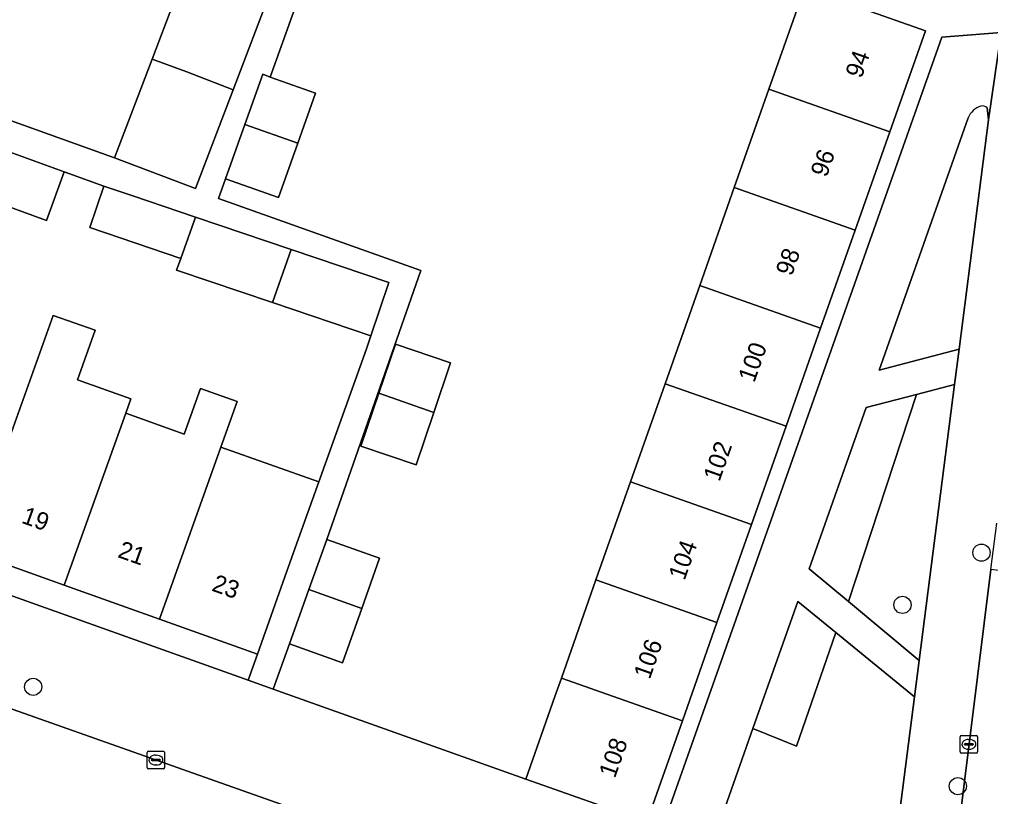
# Model space of a CAD drawing. Extents: x 159817 to 160765, y 380688 to 381638.
# Drawn here: x 160164.7 to 160220, y 381132.6 to 381176.8 of the extents above; entities that cross this region are included whole.
import ezdxf

# ---------------------------------------------------------------- set-up
doc = ezdxf.new("R2010")
doc.units = 0
for name, color, linetype in [('IMGEO_Boom', 7, 'Continuous'), ('IMGEO_Erf', 7, 'Continuous'), ('IMGEO_Groenvoorziening', 7, 'Continuous'), ('IMGEO_Kolk', 7, 'Continuous'), ('IMGEO_Pand', 7, 'Continuous'), ('IMGEO_Pand_nummerreeks', 7, 'Continuous'), ('IMGEO_Rijbaan_lokaal_open', 7, 'Continuous'), ('IMGEO_Voetpad_open', 7, 'Continuous')]:
    doc.layers.add(name, color=color, linetype=linetype)

msp = doc.modelspace()

# ---------------------------------------------------------------- linework, layer by layer
at = {"layer": 'IMGEO_Boom'}
for centre in [(160219.439, 381146.455), (160214.942, 381143.481), (160165.453, 381138.815), (160218.097, 381133.158)]:
    msp.add_circle(centre, 0.489, dxfattribs=at)
at = {"layer": 'IMGEO_Erf'}
for points in [[(160221.046, 381210.796), (160219.568, 381205.05), (160218.089, 381199.304), (160216.611, 381193.558), (160215.133, 381187.812), (160213.612, 381181.902), (160213.015, 381179.581), (160212.48, 381177.505), (160216.252, 381176.177), (160214.223, 381170.416), (160212.254, 381164.828), (160210.286, 381159.24), (160208.318, 381153.652), (160206.349, 381148.063), (160204.38, 381142.474), (160202.412, 381136.886), (160200.384, 381131.129), (160201.281, 381130.825), (160217.187, 381175.81), (160220.553, 381176.081)], [(160180.822, 381178.783), (160178.953, 381173.541), (160181.534, 381172.621), (160180.517, 381169.768), (160179.414, 381166.673), (160176.404, 381167.746), (160176.005, 381166.626), (160187.531, 381162.518), (160182.165, 381147.21), (160185.175, 381146.137), (160184.158, 381143.284), (160183.055, 381140.189), (160180.045, 381141.262), (160179.125, 381138.685), (160193.497, 381133.554), (160195.158, 381138.27), (160195.525, 381139.312), (160197.493, 381144.9), (160199.462, 381150.488), (160201.431, 381156.077), (160203.399, 381161.665), (160205.368, 381167.254), (160207.336, 381172.842), (160209.365, 381178.602)], [(160153.991, 381174.716), (160170.088, 381168.945), (160172.23, 381174.562), (160173.43, 381177.709)], [(160164.323, 381153.577), (160166.602, 381159.968), (160168.981, 381159.12), (160167.971, 381156.289), (160171.007, 381155.206), (160170.72, 381154.4), (160174.059, 381153.21), (160174.981, 381155.797), (160177.059, 381155.056), (160176.137, 381152.469), (160181.717, 381150.479), (160184.422, 381158.059), (160184.673, 381158.799), (160179.07, 381160.697), (160173.676, 381162.524), (160173.623, 381162.542), (160173.862, 381163.212), (160168.679, 381164.967), (160169.481, 381167.334), (160167.489, 381168.053), (160167.223, 381168.149), (160166.219, 381165.378), (160162.869, 381166.591)]]:
    msp.add_lwpolyline(points, dxfattribs=at)
for points in [[(160185.139, 381155.531), (160186.086, 381158.328), (160189.222, 381157.266), (160188.263, 381154.431), (160187.253, 381151.448), (160184.116, 381152.51)], [(160156.395, 381148.463), (160150.978, 381150.394), (160145.562, 381152.324), (160140.147, 381154.254), (160134.567, 381156.243), (160134.027, 381154.785), (160177.694, 381139.196), (160178.225, 381140.682), (160172.644, 381142.671), (160167.227, 381144.602), (160161.811, 381146.532)]]:
    msp.add_lwpolyline(points, close=True, dxfattribs=at)
at = {"layer": 'IMGEO_Groenvoorziening'}
for points in [[(160219.848, 381171.104), (160219.756, 381171.779)], [(160218.686, 381171.22), (160213.62, 381156.844), (160218.169, 381158.049), (160219.848, 381171.104)], [(160215.622, 381138.248), (160211.146, 381141.909), (160208.918, 381135.436), (160206.428, 381136.435), (160204.587, 381131.21)], [(160214.532, 381129.693), (160215.622, 381138.248)]]:
    msp.add_lwpolyline(points, dxfattribs=at)
for points in [[(160215.888, 381140.319), (160217.909, 381156.029), (160215.733, 381155.464), (160211.864, 381143.673)], [(160211.864, 381143.673), (160215.733, 381155.464), (160212.872, 381154.722), (160209.633, 381145.53)], [(160206.428, 381136.435), (160208.918, 381135.436), (160211.146, 381141.909), (160208.981, 381143.679)]]:
    msp.add_lwpolyline(points, close=True, dxfattribs=at)
for centre, radius, start, end in [((160219.75, 381170.795), 1.146, 107.4196, 158.2101), ((160219.491, 381171.545), 0.354, 41.5289, 103.7817)]:
    msp.add_arc(centre, radius, start, end, dxfattribs=at)
at = {"layer": 'IMGEO_Kolk'}
for p, q in [((160218.222, 381135.112), (160218.222, 381135.964)), ((160218.297, 381136.038), (160219.149, 381136.038)), ((160218.524, 381135.581), (160218.922, 381135.581)), ((160218.71, 381135.818), (160218.735, 381135.818)), ((160219.223, 381135.964), (160219.223, 381135.112)), ((160171.939, 381134.218), (160171.939, 381135.07)), ((160172.014, 381135.144), (160172.866, 381135.144)), ((160172.94, 381135.07), (160172.94, 381134.218)), ((160219.149, 381135.038), (160218.297, 381135.038)), ((160218.481, 381135.532), (160218.481, 381135.544)), ((160218.919, 381135.495), (160218.521, 381135.495)), ((160218.733, 381135.258), (160218.708, 381135.258)), ((160218.965, 381135.544), (160218.965, 381135.532)), ((160172.198, 381134.638), (160172.198, 381134.65)), ((160172.636, 381134.601), (160172.238, 381134.601)), ((160172.241, 381134.687), (160172.639, 381134.687)), ((160172.427, 381134.924), (160172.452, 381134.924)), ((160172.682, 381134.65), (160172.682, 381134.638)), ((160172.866, 381134.144), (160172.014, 381134.144)), ((160172.45, 381134.364), (160172.425, 381134.364))]:
    msp.add_line(p, q, dxfattribs=at)
for points in [[(160218.222, 381135.112), (160218.222, 381135.964)], [(160218.297, 381136.038), (160219.149, 381136.038)], [(160219.223, 381135.964), (160219.223, 381135.112)], [(160171.939, 381134.218), (160171.939, 381135.07)], [(160172.014, 381135.144), (160172.866, 381135.144)], [(160172.94, 381135.07), (160172.94, 381134.218)], [(160219.149, 381135.038), (160218.297, 381135.038)], [(160172.866, 381134.144), (160172.014, 381134.144)]]:
    msp.add_lwpolyline(points, dxfattribs=at)
for centre, radius, start, end in [((160218.299, 381135.962), 0.0765, 91.552, 178.448), ((160218.299, 381135.962), 0.0765, 91.552, 178.448), ((160218.521, 381135.541), 0.0403, 85.8775, 175.7526), ((160218.926, 381135.543), 0.0386, 1.7309, 96.639), ((160219.147, 381135.962), 0.0765, 1.552, 88.448), ((160219.147, 381135.962), 0.0765, 1.552, 88.448), ((160172.016, 381135.068), 0.0765, 91.552, 178.448), ((160172.016, 381135.068), 0.0765, 91.552, 178.448), ((160172.864, 381135.068), 0.0765, 1.552, 88.448), ((160172.864, 381135.068), 0.0765, 1.552, 88.448), ((160218.299, 381135.114), 0.0765, 181.552, 268.448), ((160218.299, 381135.114), 0.0765, 181.552, 268.448), ((160218.518, 381135.531), 0.0366, 178.938, 274.7102), ((160218.922, 381135.538), 0.043, 264.8664, 352.4533), ((160219.147, 381135.114), 0.0765, 271.552, 358.448), ((160219.147, 381135.114), 0.0765, 271.552, 358.448), ((160172.238, 381134.647), 0.0403, 85.8775, 175.7526), ((160172.235, 381134.637), 0.0366, 178.938, 274.7102), ((160172.639, 381134.644), 0.043, 264.8664, 352.4533), ((160172.643, 381134.649), 0.0386, 1.7309, 96.639), ((160172.016, 381134.22), 0.0765, 181.552, 268.448), ((160172.016, 381134.22), 0.0765, 181.552, 268.448), ((160172.864, 381134.22), 0.0765, 271.552, 358.448), ((160172.864, 381134.22), 0.0765, 271.552, 358.448)]:
    msp.add_arc(centre, radius, start, end, dxfattribs=at)
for centre, major_axis, ratio, start_param, end_param in [((160218.709, 381135.538), (-0.387, 0.002), 0.722429, 4.712389, 7.853982), ((160218.734, 381135.538), (-0.39, 0.002), 0.717154, 1.570796, 4.712389), ((160172.426, 381134.644), (-0.387, 0.002), 0.722429, 4.712389, 7.853982), ((160172.451, 381134.644), (-0.39, 0.002), 0.717154, 1.570796, 4.712389)]:
    msp.add_ellipse(centre, major_axis=major_axis, ratio=ratio, start_param=start_param, end_param=end_param, dxfattribs=at)
at = {"layer": 'IMGEO_Pand'}
for points in [[(160216.252, 381176.177), (160212.48, 381177.505), (160213.015, 381179.581), (160208.447, 381180.979), (160208.302, 381180.422), (160207.961, 381179.097), (160209.365, 381178.602), (160207.336, 381172.842), (160214.223, 381170.416)], [(160179.028, 381178.555), (160174.422, 381180.311), (160174.33, 381180.069), (160173.43, 381177.709), (160172.23, 381174.562), (160174.202, 381173.828), (160176.84, 381172.816)], [(160176.84, 381172.816), (160174.202, 381173.828), (160172.23, 381174.562), (160170.088, 381168.945), (160174.693, 381167.188)], [(160181.534, 381172.621), (160178.953, 381173.541), (160178.524, 381173.694), (160177.504, 381170.832), (160180.517, 381169.768)], [(160214.223, 381170.416), (160207.336, 381172.842), (160205.368, 381167.254), (160212.254, 381164.828)], [(160177.504, 381170.832), (160176.404, 381167.746), (160179.414, 381166.673), (160180.517, 381169.768)], [(160167.223, 381168.149), (160163.873, 381169.362), (160162.869, 381166.591), (160166.219, 381165.378)], [(160174.701, 381165.566), (160171.066, 381166.797), (160169.481, 381167.334), (160168.679, 381164.967), (160173.862, 381163.212)], [(160203.399, 381161.665), (160210.286, 381159.24), (160212.254, 381164.828), (160205.368, 381167.254)], [(160180.148, 381163.721), (160174.701, 381165.566), (160173.862, 381163.212), (160173.623, 381162.542), (160173.676, 381162.524), (160179.07, 381160.697)], [(160185.702, 381161.84), (160180.148, 381163.721), (160179.07, 381160.697), (160184.673, 381158.799)], [(160203.399, 381161.665), (160201.431, 381156.077), (160208.318, 381153.652), (160210.286, 381159.24)], [(160169.738, 381151.646), (160170.72, 381154.4), (160171.007, 381155.206), (160167.971, 381156.289), (160168.981, 381159.12), (160166.602, 381159.968), (160164.323, 381153.577), (160161.811, 381146.532), (160167.227, 381144.602)], [(160185.139, 381155.531), (160188.263, 381154.431), (160189.222, 381157.266), (160186.086, 381158.328)], [(160199.462, 381150.488), (160206.349, 381148.063), (160208.318, 381153.652), (160201.431, 381156.077)], [(160172.644, 381142.671), (160176.137, 381152.469), (160177.059, 381155.056), (160174.981, 381155.797), (160174.059, 381153.21), (160170.72, 381154.4), (160169.738, 381151.646), (160167.227, 381144.602)], [(160188.263, 381154.431), (160185.139, 381155.531), (160184.116, 381152.51), (160187.253, 381151.448)], [(160172.644, 381142.671), (160178.225, 381140.682), (160179.904, 381145.392), (160180.737, 381147.729), (160181.717, 381150.479), (160176.137, 381152.469)], [(160199.462, 381150.488), (160197.493, 381144.9), (160204.38, 381142.474), (160206.349, 381148.063)], [(160184.158, 381143.284), (160185.175, 381146.137), (160182.165, 381147.21), (160181.145, 381144.348)], [(160202.412, 381136.886), (160204.38, 381142.474), (160197.493, 381144.9), (160195.525, 381139.312)], [(160184.158, 381143.284), (160181.145, 381144.348), (160180.045, 381141.262), (160183.055, 381140.189)], [(160202.412, 381136.886), (160195.525, 381139.312), (160195.158, 381138.27), (160193.497, 381133.554), (160200.384, 381131.129)]]:
    msp.add_lwpolyline(points, close=True, dxfattribs=at)
at = {"layer": 'IMGEO_Rijbaan_lokaal_open'}
for points in [[(160085.799, 381159.896), (160085.986, 381159.435), (160086.066, 381159.245), (160086.112, 381159.128), (160093.302, 381156.554), (160121.03, 381146.824), (160125.069, 381145.386), (160156.523, 381134.111), (160186.491, 381123.368), (160203.779, 381117.171), (160205.8, 381122.85), (160205.469, 381122.967), (160135.586, 381147.67)], [(160225.646, 381144.801), (160219.974, 381145.503), (160218.055, 381130.055), (160217.752, 381128.647)]]:
    msp.add_lwpolyline(points, dxfattribs=at)
at = {"layer": 'IMGEO_Voetpad_open'}
for points in [[(160240.565, 381248.07), (160239.679, 381250), (160239.37, 381250.674), (160236.556, 381244.206), (160228.759, 381216.983), (160225.86, 381204.829), (160223.787, 381195.191), (160221.984, 381185.498), (160220.553, 381176.081), (160219.848, 381171.104), (160218.169, 381158.049), (160217.909, 381156.029), (160215.888, 381140.319), (160215.622, 381138.248), (160214.532, 381129.693), (160217.752, 381128.647), (160218.055, 381130.055), (160219.974, 381145.503), (160220.311, 381148.131)], [(160191.898, 381212.922), (160190.075, 381207.84), (160187.871, 381201.698), (160187.003, 381199.526), (160187.429, 381199.356), (160186.135, 381196.121), (160184.596, 381192.275), (160184.38, 381192.361), (160183.343, 381189.769), (160181.437, 381184.649), (160181.225, 381184.125), (160181.546, 381183.995), (160179.476, 381178.875), (160179.202, 381178.986), (160179.028, 381178.555), (160176.84, 381172.816), (160174.693, 381167.188), (160170.088, 381168.945), (160153.991, 381174.716)], [(160163.873, 381169.362), (160167.223, 381168.149), (160167.489, 381168.053), (160169.481, 381167.334), (160171.066, 381166.797), (160174.701, 381165.566), (160180.148, 381163.721), (160185.702, 381161.84), (160184.673, 381158.799), (160184.422, 381158.059), (160181.717, 381150.479), (160180.737, 381147.729), (160179.904, 381145.392), (160178.225, 381140.682), (160177.694, 381139.196), (160179.125, 381138.685), (160180.045, 381141.262), (160181.145, 381144.348), (160182.165, 381147.21), (160187.531, 381162.518), (160176.005, 381166.626), (160176.404, 381167.746), (160177.504, 381170.832), (160178.524, 381173.694), (160178.953, 381173.541), (160180.822, 381178.783)], [(160219.756, 381171.779), (160219.848, 381171.104), (160220.553, 381176.081), (160217.187, 381175.81), (160201.281, 381130.825), (160205.235, 381129.276), (160205.303, 381129.259)], [(160212.872, 381154.722), (160215.733, 381155.464), (160217.909, 381156.029), (160218.169, 381158.049), (160213.62, 381156.844), (160218.686, 381171.22)], [(160177.694, 381139.196), (160134.027, 381154.785), (160131.18, 381155.746), (160130.876, 381154.914)], [(160204.587, 381131.21), (160206.428, 381136.435), (160208.981, 381143.679), (160211.146, 381141.909), (160215.622, 381138.248), (160215.888, 381140.319), (160211.864, 381143.673), (160209.633, 381145.53), (160212.872, 381154.722)], [(160134.786, 381148.029), (160135.586, 381147.67), (160205.469, 381122.967), (160205.8, 381122.85)], [(160212.024, 381126.869), (160205.303, 381129.259), (160205.235, 381129.276), (160201.281, 381130.825), (160200.384, 381131.129), (160193.497, 381133.554), (160179.125, 381138.685), (160177.694, 381139.196)]]:
    msp.add_lwpolyline(points, dxfattribs=at)
for centre, radius, start, end in [((160219.75, 381170.795), 1.146, 107.4196, 158.2101), ((160219.491, 381171.545), 0.354, 41.5289, 103.7817)]:
    msp.add_arc(centre, radius, start, end, dxfattribs=at)

# ---------------------------------------------------------------- texts
at = {"layer": 'IMGEO_Pand_nummerreeks'}
for s, rotation, p in [('94', 70.5941, (160212.609, 381173.419)), ('96', 70.5954, (160210.625, 381167.788)), ('98', 70.5954, (160208.643, 381162.16)), ('100', 70.5954, (160206.506, 381156.096)), ('102', 70.5954, (160204.521, 381150.459)), ('19', 340.3819, (160164.735, 381148.165)), ('21', 340.3824, (160170.214, 381146.213)), ('104', 70.5954, (160202.537, 381144.83)), ('23', 340.3824, (160175.564, 381144.305)), ('106', 70.5954, (160200.554, 381139.199)), ('108', 70.5954, (160198.572, 381133.572))]:
    msp.add_text(s, height=1, rotation=rotation, dxfattribs=at).set_placement(p)

doc.saveas('drawing.dxf')
